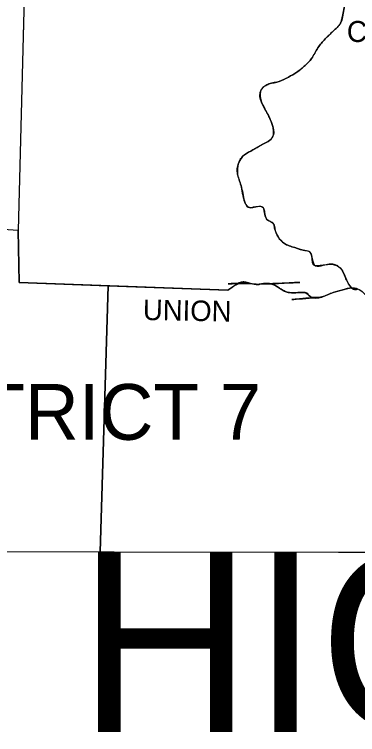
# Model space of a CAD drawing. Extents: x 3046 to 131673, y -8885 to 10756.
# Drawn here: x 103569 to 104255, y 4715 to 6157 of the extents above; entities that cross this region are included whole.
import ezdxf

# ---------------------------------------------------------------- set-up
doc = ezdxf.new("R2010")
doc.units = 0
for name, color, linetype in [('1', 7, 'Continuous'), ('2', 7, 'Continuous'), ('3', 7, 'Continuous'), ('R_Annotation', 7, 'Continuous')]:
    doc.layers.add(name, color=color, linetype=linetype)

msp = doc.modelspace()

# ---------------------------------------------------------------- linework, layer by layer
at = {"layer": '1'}
for points in [[(103588.89674506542, 6217.377333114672), (103576.17745635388, 5724.260297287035), (103444.09253611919, 5733.06595852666), (103443.11412921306, 5696.86490635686), (103267.00090220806, 5707.62738140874)], [(103588.89674506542, 6217.377333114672), (103576.17745635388, 5724.260297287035), (103444.09253611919, 5733.06595852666), (103443.11412921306, 5696.86490635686), (103267.00090220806, 5707.62738140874)], [(102421.65741198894, 5874.934947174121), (102423.61422561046, 5083.403831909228), (106009.47521109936, 5077.533390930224)], [(102421.65741198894, 5874.934947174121), (102423.61422561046, 5083.403831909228), (106009.47521109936, 5077.533390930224)], [(103995.91398108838, 5604.894665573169), (103578.13427001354, 5620.54917462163), (103576.08045633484, 5724.266763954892)], [(103995.91398108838, 5604.894665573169), (103578.13427001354, 5620.54917462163), (103576.08045633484, 5724.266763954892)], [(103756.26641412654, 5613.874433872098), (103740.74359051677, 5081.247549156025)], [(103756.26641412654, 5613.874433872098), (103740.74359051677, 5081.247549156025)]]:
    msp.add_lwpolyline(points, dxfattribs=at)
for points in [[(104237.08427846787, 6257.806639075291), (104234.64524447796, 6196.830789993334), (104227.79639682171, 6166.5001787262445), (104220.94754901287, 6139.104787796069), (104206.2714468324, 6123.450278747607), (104190.61693770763, 6107.795769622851), (104175.94083552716, 6090.184446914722), (104163.2215468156, 6068.659496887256), (104150.50225825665, 6054.961801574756), (104133.86934222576, 6041.264106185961), (104117.23642638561, 6031.4800379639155), (104098.6466969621, 6022.67437649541), (104078.10015365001, 6017.782342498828), (104063.42405146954, 6007.019867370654), (104062.44564456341, 5983.538103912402), (104079.07856055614, 5950.272272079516), (104084.949001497, 5934.61776295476), (104086.90581515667, 5916.028033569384), (104080.05696730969, 5905.2655584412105), (104064.40245818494, 5896.459897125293), (104045.8127287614, 5885.697422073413), (104029.17981292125, 5875.913353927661), (104017.43893111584, 5859.280438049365), (104015.48211745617, 5836.777081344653), (104023.3093719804, 5810.360097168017), (104026.24459235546, 5794.705588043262), (104038.96388110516, 5770.245417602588), (104048.74794925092, 5771.223824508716), (104066.3592718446, 5770.245417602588), (104068.31608550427, 5765.3533836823), (104069.2944924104, 5760.461349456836), (104073.20811969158, 5747.7420608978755), (104087.88422187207, 5736.979585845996), (104089.84103549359, 5727.19551762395), (104098.6466969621, 5708.60578816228), (104113.32279914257, 5695.88649960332), (104124.08527408, 5691.972872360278), (104146.58863097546, 5685.12402455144), (104158.32951278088, 5682.188804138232), (104171.04880133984, 5653.815006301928), (104186.70331042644, 5654.793413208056), (104198.44419223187, 5656.750226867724), (104218.01232863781, 5651.858192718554), (104226.81798991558, 5640.117311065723), (104235.62365138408, 5620.54917462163), (104247.36453318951, 5606.851479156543), (104255.19178771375, 5606.851479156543)], [(104237.08427846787, 6257.806639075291), (104234.64524447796, 6196.830789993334), (104227.79639682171, 6166.5001787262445), (104220.94754901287, 6139.104787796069), (104206.2714468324, 6123.450278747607), (104190.61693770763, 6107.795769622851), (104175.94083552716, 6090.184446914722), (104163.2215468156, 6068.659496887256), (104150.50225825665, 6054.961801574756), (104133.86934222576, 6041.264106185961), (104117.23642638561, 6031.4800379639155), (104098.6466969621, 6022.67437649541), (104078.10015365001, 6017.782342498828), (104063.42405146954, 6007.019867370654), (104062.44564456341, 5983.538103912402), (104079.07856055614, 5950.272272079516), (104084.949001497, 5934.61776295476), (104086.90581515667, 5916.028033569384), (104080.05696730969, 5905.2655584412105), (104064.40245818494, 5896.459897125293), (104045.8127287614, 5885.697422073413), (104029.17981292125, 5875.913353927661), (104017.43893111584, 5859.280438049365), (104015.48211745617, 5836.777081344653), (104023.3093719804, 5810.360097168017), (104026.24459235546, 5794.705588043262), (104038.96388110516, 5770.245417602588), (104048.74794925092, 5771.223824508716), (104066.3592718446, 5770.245417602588), (104068.31608550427, 5765.3533836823), (104069.2944924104, 5760.461349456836), (104073.20811969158, 5747.7420608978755), (104087.88422187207, 5736.979585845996), (104089.84103549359, 5727.19551762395), (104098.6466969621, 5708.60578816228), (104113.32279914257, 5695.88649960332), (104124.08527408, 5691.972872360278), (104146.58863097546, 5685.12402455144), (104158.32951278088, 5682.188804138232), (104171.04880133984, 5653.815006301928), (104186.70331042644, 5654.793413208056), (104198.44419223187, 5656.750226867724), (104218.01232863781, 5651.858192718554), (104226.81798991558, 5640.117311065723), (104235.62365138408, 5620.54917462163), (104247.36453318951, 5606.851479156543), (104255.19178771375, 5606.851479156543)], [(103995.91398108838, 5604.894665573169), (104011.56849017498, 5615.657140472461), (104026.24459235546, 5621.5275813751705), (104040.92069472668, 5618.592361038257), (104056.5752036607, 5616.635547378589), (104070.27289912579, 5618.592361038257), (104087.88422187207, 5615.657140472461), (104102.56032420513, 5606.851479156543), (104119.19324004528, 5600.0026314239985), (104135.82615588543, 5600.0026314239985), (104150.50225825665, 5600.0026314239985), (104163.2215468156, 5591.196970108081), (104186.70331042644, 5592.175376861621), (104206.2714468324, 5600.0026314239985), (104225.83958316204, 5605.873072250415), (104252.25656722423, 5608.80829281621), (104275.73833087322, 5592.175376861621), (104292.37124671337, 5578.477681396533), (104306.06894214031, 5562.823172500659), (104315.85301032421, 5545.2118497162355), (104326.6154852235, 5535.427781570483), (104344.22680796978, 5528.578933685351), (104357.92450343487, 5525.643713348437), (104374.55741946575, 5520.7516791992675), (104383.36308070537, 5516.838051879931), (104391.19033526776, 5498.2483224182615), (104403.90962378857, 5472.809745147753), (104428.36979438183, 5464.004083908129), (104458.70040564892, 5475.744965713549), (104483.16057605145, 5482.593813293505), (104500.77189875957, 5488.46425427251), (104511.53437388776, 5492.377881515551), (104521.31844207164, 5493.356288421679), (104518.38322150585, 5495.313102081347), (104530.12410331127, 5498.2483224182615), (104540.88657824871, 5490.421067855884), (104547.73542605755, 5479.658592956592), (104559.47630790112, 5464.004083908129), (104570.23878280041, 5450.306388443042), (104581.00125792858, 5445.414354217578), (104591.76373282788, 5451.2847951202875), (104606.43983500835, 5446.392761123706), (104619.15912375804, 5441.500726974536), (104633.83522593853, 5437.587099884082), (104646.55451465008, 5436.608692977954), (104663.18743045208, 5432.695065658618), (104675.90671904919, 5425.846218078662), (104687.64760089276, 5418.99737019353), (104699.38848269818, 5406.27808163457), (104711.12936450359, 5386.7099453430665), (104715.04299178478, 5371.05543621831), (104728.74068724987, 5355.400927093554), (104741.45997596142, 5355.400927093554), (104760.0497054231, 5329.962349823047), (104766.89855307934, 5320.178281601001), (104781.57465545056, 5302.56695889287), (104792.33713034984, 5302.56695889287), (104812.88367347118, 5298.653331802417)], [(103995.91398108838, 5604.894665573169), (104011.56849017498, 5615.657140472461), (104026.24459235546, 5621.5275813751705), (104040.92069472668, 5618.592361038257), (104056.5752036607, 5616.635547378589), (104070.27289912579, 5618.592361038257), (104087.88422187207, 5615.657140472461), (104102.56032420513, 5606.851479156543), (104119.19324004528, 5600.0026314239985), (104135.82615588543, 5600.0026314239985), (104150.50225825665, 5600.0026314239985), (104163.2215468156, 5591.196970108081), (104186.70331042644, 5592.175376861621), (104206.2714468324, 5600.0026314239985), (104225.83958316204, 5605.873072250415), (104252.25656722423, 5608.80829281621), (104275.73833087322, 5592.175376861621), (104292.37124671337, 5578.477681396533), (104306.06894214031, 5562.823172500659), (104315.85301032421, 5545.2118497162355), (104326.6154852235, 5535.427781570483), (104344.22680796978, 5528.578933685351), (104357.92450343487, 5525.643713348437), (104374.55741946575, 5520.7516791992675), (104383.36308070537, 5516.838051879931), (104391.19033526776, 5498.2483224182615), (104403.90962378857, 5472.809745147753), (104428.36979438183, 5464.004083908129), (104458.70040564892, 5475.744965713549), (104483.16057605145, 5482.593813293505), (104500.77189875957, 5488.46425427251), (104511.53437388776, 5492.377881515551), (104521.31844207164, 5493.356288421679), (104518.38322150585, 5495.313102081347), (104530.12410331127, 5498.2483224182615), (104540.88657824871, 5490.421067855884), (104547.73542605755, 5479.658592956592), (104559.47630790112, 5464.004083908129), (104570.23878280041, 5450.306388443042), (104581.00125792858, 5445.414354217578), (104591.76373282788, 5451.2847951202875), (104606.43983500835, 5446.392761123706), (104619.15912375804, 5441.500726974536), (104633.83522593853, 5437.587099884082), (104646.55451465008, 5436.608692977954), (104663.18743045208, 5432.695065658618), (104675.90671904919, 5425.846218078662), (104687.64760089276, 5418.99737019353), (104699.38848269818, 5406.27808163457), (104711.12936450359, 5386.7099453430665), (104715.04299178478, 5371.05543621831), (104728.74068724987, 5355.400927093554), (104741.45997596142, 5355.400927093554), (104760.0497054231, 5329.962349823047), (104766.89855307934, 5320.178281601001), (104781.57465545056, 5302.56695889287), (104792.33713034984, 5302.56695889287), (104812.88367347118, 5298.653331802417)]]:
    msp.add_spline(points, degree=3, dxfattribs=at)
at = {"layer": 'R_Annotation'}
for p, q in [((103588.89674506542, 6217.377333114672), (103576.08045633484, 5724.266763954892)), ((103756.26641412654, 5613.874433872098), (103740.74359051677, 5081.247549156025)), ((103740.74359051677, 5081.247549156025), (103756.26641412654, 5613.874433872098)), ((103995.91398108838, 5604.894665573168), (103756.26641412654, 5613.874433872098)), ((103756.26641412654, 5613.874433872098), (103995.91398108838, 5604.894665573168)), ((104011.56849017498, 5615.657140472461), (104026.24459235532, 5621.527581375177)), ((104026.24459235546, 5621.5275813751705), (104031.41696694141, 5620.766988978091)), ((104031.41696694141, 5620.76698897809), (104033.55187765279, 5620.254488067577)), ((104034.81262439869, 5619.933282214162), (104037.22442127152, 5619.330202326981)), ((104063.42509927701, 5617.470504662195), (104066.84895005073, 5618.2204441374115)), ((104068.49074441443, 5618.473637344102), (104070.27289912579, 5618.592361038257)), ((104070.27289912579, 5618.592361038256), (104079.08503790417, 5618.058886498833)), ((104079.08503790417, 5618.058886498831), (104087.88422187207, 5615.657140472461)), ((104091.813874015, 5613.660706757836), (104095.39345936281, 5611.345137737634)), ((104097.23152067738, 5610.087265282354), (104098.8874515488, 5608.984154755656)), ((104225.83958316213, 5605.87307225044), (104243.53112397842, 5610.17400937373)), ((104102.56032420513, 5606.851479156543), (104109.1567881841, 5603.198928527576)), ((104109.1567881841, 5603.198928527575), (104110.65170703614, 5602.414280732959)), ((104110.65170703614, 5602.414280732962), (104116.58782989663, 5600.255141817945)), ((104116.58782989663, 5600.255141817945), (104119.19324004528, 5600.0026314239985)), ((104153.97707314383, 5598.759042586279), (104156.9608794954, 5595.952589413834)), ((104188.87412338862, 5592.977191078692), (104191.60593975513, 5594.068024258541)), ((104191.60593975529, 5594.068024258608), (104196.4626671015, 5596.12803246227)), ((104196.46266710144, 5596.128032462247), (104201.3317502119, 5598.168526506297)), ((104201.33175021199, 5598.168526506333), (104204.7990627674, 5599.492504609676)), ((104204.7990627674, 5599.492504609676), (104206.2714468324, 5600.002631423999)), ((104206.2714468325, 5600.002631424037), (104215.69116409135, 5602.964978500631)), ((104215.69116409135, 5602.96497850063), (104225.83958316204, 5605.873072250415)), ((104159.89519736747, 5592.969741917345), (104161.38718769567, 5591.898698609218)), ((104161.38718769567, 5591.898698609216), (104163.2215468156, 5591.196970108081)), ((104174.99264871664, 5590.176320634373), (104180.97773212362, 5590.725886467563)), ((104180.97773212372, 5590.725886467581), (104183.73743536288, 5591.2914970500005)), ((104183.73743536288, 5591.291497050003), (104186.7033104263, 5592.175376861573)), ((104186.70331042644, 5592.175376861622), (104188.87412338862, 5592.977191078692)), ((103113.39078486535, 5082.274593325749), (103740.74359051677, 5081.247549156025)), ((103740.74359051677, 5081.247549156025), (104880.7243214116, 5079.381277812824))]:
    msp.add_line(p, q, dxfattribs=at)
for points in [[(103576.08045633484, 5724.266763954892), (103444.09253611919, 5733.06595852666), (103443.11412921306, 5696.86490635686), (103267.00090220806, 5707.62738140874)], [(103576.08045633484, 5724.266763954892), (103578.13427001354, 5620.54917462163), (103756.26641412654, 5613.874433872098)], [(103756.26641412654, 5613.874433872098), (103578.13427001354, 5620.54917462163), (103576.08045633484, 5724.266763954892)], [(104255.4074246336, 5607.249735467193), (104255.19178771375, 5606.851479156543)]]:
    msp.add_lwpolyline(points, dxfattribs=at)
for points in [[(104062.76730762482, 5895.513607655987), (104064.40245818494, 5896.459897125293), (104080.05696730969, 5905.2655584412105), (104086.90581515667, 5916.028033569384), (104087.31956126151, 5920.659311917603), (104087.06390239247, 5925.379459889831), (104086.23999649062, 5930.07132704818), (104084.949001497, 5934.61776295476), (104079.07856055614, 5950.272272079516), (104075.1593298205, 5958.712599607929), (104070.80542871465, 5966.985054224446), (104066.42986453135, 5975.217575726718), (104062.44564456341, 5983.538103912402), (104059.98287036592, 5995.270110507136), (104060.81533309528, 6001.34864555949), (104063.42405146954, 6007.019867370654), (104064.88231507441, 6008.975697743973), (104066.46582220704, 6010.725926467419), (104069.9730795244, 6013.6719131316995), (104078.10015365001, 6017.782342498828), (104083.25050255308, 6019.193255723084), (104088.48277216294, 6020.111812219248), (104093.66036834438, 6021.08864235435), (104098.6466969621, 6022.67437649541), (104117.23642638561, 6031.4800379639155), (104133.86934222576, 6041.264106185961), (104150.50225825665, 6054.961801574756), (104163.2215468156, 6068.659496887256), (104166.64652242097, 6073.894243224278), (104169.60202341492, 6079.422534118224), (104172.54710828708, 6084.950543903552), (104175.94083552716, 6090.184446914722), (104190.61693770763, 6107.795769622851), (104198.42488536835, 6115.643399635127), (104206.2714468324, 6123.450278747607), (104214.26704404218, 6130.707505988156), (104217.97779579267, 6134.58586323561), (104220.94754901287, 6139.104787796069), (104221.71287693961, 6140.745184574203), (104222.3945192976, 6142.403100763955), (104223.53993208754, 6145.764682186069), (104225.19156342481, 6152.623176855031), (104227.79639682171, 6166.5001787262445), (104231.68915429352, 6181.578272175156), (104234.64524447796, 6196.830789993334), (104235.34530635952, 6204.41818446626), (104235.85551729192, 6212.010610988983), (104236.45989263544, 6227.20668069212), (104237.07900152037, 6257.6165302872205)], [(104243.53112397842, 5610.174009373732), (104235.62365138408, 5620.54917462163), (104233.24202139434, 5625.406227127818), (104231.19415954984, 5630.3451736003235), (104229.15962825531, 5635.278154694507), (104226.81798991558, 5640.117311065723), (104223.25149066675, 5646.369532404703), (104218.01232863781, 5651.858192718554), (104215.62705542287, 5653.408541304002), (104213.21806295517, 5654.646573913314), (104208.34164800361, 5656.273840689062), (104198.44419223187, 5656.750226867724), (104186.70331042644, 5654.793413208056), (104178.87479352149, 5653.910495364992), (104171.04880133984, 5653.815006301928), (104167.97501701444, 5655.115314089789), (104166.1454655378, 5658.139096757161), (104164.57852300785, 5667.193803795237), (104163.06689750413, 5676.652561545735), (104159.99570774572, 5681.409088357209), (104158.32951278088, 5682.188804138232), (104146.58863097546, 5685.12402455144), (104124.08527408, 5691.972872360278), (104113.32279914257, 5695.88649960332), (104105.2078176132, 5701.129294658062), (104101.76044937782, 5704.643393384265), (104098.6466969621, 5708.60578816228), (104093.56590576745, 5717.697563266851), (104089.84103549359, 5727.19551762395), (104089.22899980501, 5729.607461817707), (104088.91159864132, 5732.113622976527), (104088.56971249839, 5734.606748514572), (104087.88422187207, 5736.979585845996), (104084.91370739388, 5740.200597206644), (104080.49755427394, 5742.312712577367), (104076.10570940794, 5744.448883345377), (104073.20811969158, 5747.7420608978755), (104069.2944924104, 5760.461349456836), (104068.31608550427, 5765.3533836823), (104067.8426010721, 5767.97744058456), (104066.3592718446, 5770.245417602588), (104065.27008352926, 5770.944299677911), (104064.17768793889, 5771.488145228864), (104061.9847075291, 5772.170731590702), (104057.57601796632, 5772.3355191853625), (104053.15612469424, 5771.699857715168), (104050.94913964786, 5771.381882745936), (104048.74794925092, 5771.223824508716), (104046.29675386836, 5770.811701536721), (104043.84597519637, 5770.085771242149), (104041.40016651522, 5769.684265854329), (104038.96388110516, 5770.245417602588), (104037.34698979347, 5771.1944231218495), (104035.89505226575, 5772.274105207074), (104033.43858512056, 5774.779748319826), (104029.98310837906, 5780.855895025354), (104027.8381958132, 5787.741845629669), (104026.24459235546, 5794.705588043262), (104025.44489193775, 5798.627029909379), (104024.7750640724, 5802.562752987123), (104023.3093719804, 5810.360097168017), (104021.49284116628, 5816.984858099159), (104019.37642678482, 5823.57664696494), (104017.26967137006, 5830.164406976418), (104015.48211745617, 5836.777081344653), (104014.80890854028, 5847.990113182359), (104017.43893111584, 5859.280438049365), (104019.49373283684, 5864.182851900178), (104022.046241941, 5868.767268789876), (104025.23031608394, 5872.766499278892), (104029.17981292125, 5875.913353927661), (104045.8127287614, 5885.697422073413), (104062.76730762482, 5895.513607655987)], [(104060.00072456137, 5616.792289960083), (104063.42509927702, 5617.470504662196), (104063.42509927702, 5617.470504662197)], [(104037.22442127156, 5619.330202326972), (104037.22442127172, 5619.330202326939), (104040.92069472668, 5618.592361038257), (104040.92069472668, 5618.592361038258)], [(104243.53112397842, 5610.17400937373), (104225.83958316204, 5605.873072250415), (104206.2714468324, 5600.0026314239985), (104201.33175021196, 5598.168526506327), (104196.46266710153, 5596.128032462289), (104191.60593975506, 5594.068024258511), (104186.70331042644, 5592.175376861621), (104180.97773212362, 5590.725886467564), (104174.99264871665, 5590.176320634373), (104168.99245526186, 5590.38168122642), (104163.2215468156, 5591.196970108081), (104159.89519736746, 5592.969741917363), (104156.96087949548, 5595.952589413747), (104153.97707314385, 5598.759042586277), (104150.50225825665, 5600.0026314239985), (104135.82615588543, 5600.0026314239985), (104119.19324004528, 5600.0026314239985), (104110.65170703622, 5602.414280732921), (104102.56032420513, 5606.851479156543), (104098.88745154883, 5608.984154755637), (104095.39345936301, 5611.345137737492), (104091.81387401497, 5613.6607067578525), (104087.88422187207, 5615.657140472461), (104070.27289912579, 5618.592361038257), (104066.8489500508, 5618.220444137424), (104063.42509927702, 5617.470504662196), (104060.00072456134, 5616.79228996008), (104056.5752036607, 5616.635547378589), (104040.92069472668, 5618.592361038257), (104037.22442127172, 5619.330202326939), (104033.55187765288, 5620.25448806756), (104026.24459235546, 5621.5275813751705), (104011.56849017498, 5615.657140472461), (103995.91398108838, 5604.894665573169)], [(104033.55187765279, 5620.254488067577), (104033.55187765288, 5620.25448806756), (104034.81262439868, 5619.933282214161)], [(104066.84895005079, 5618.220444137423), (104066.8489500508, 5618.220444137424), (104068.49074441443, 5618.473637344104)], [(104087.88422187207, 5615.657140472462), (104087.88422187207, 5615.657140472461), (104091.81387401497, 5613.6607067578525), (104091.81387401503, 5613.6607067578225)], [(104095.39345936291, 5611.345137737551), (104095.39345936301, 5611.345137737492), (104097.2315206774, 5610.087265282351)], [(104098.88745154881, 5608.984154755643), (104098.88745154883, 5608.984154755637), (104102.56032420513, 5606.851479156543)], [(104255.19178771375, 5606.851479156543), (104247.36453318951, 5606.851479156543), (104243.53112397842, 5610.174009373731)], [(104119.19324004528, 5600.0026314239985), (104135.82615588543, 5600.0026314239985), (104150.50225825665, 5600.0026314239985)], [(104150.50225825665, 5600.002631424), (104153.97707314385, 5598.759042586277), (104153.97707314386, 5598.759042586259)], [(104156.96087949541, 5595.952589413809), (104156.96087949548, 5595.952589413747), (104159.89519736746, 5592.969741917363), (104159.89519736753, 5592.9697419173)], [(104168.99245526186, 5590.381681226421), (104168.99245526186, 5590.38168122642), (104174.99264871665, 5590.176320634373), (104174.99264871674, 5590.176320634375)], [(104163.22154681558, 5591.196970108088), (104163.2215468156, 5591.196970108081), (104168.99245526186, 5590.381681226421)]]:
    msp.add_spline(points, degree=3, dxfattribs=at)
for points in [[(103995.91398108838, 5604.894665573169), (104000.72916449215, 5609.118662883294), (104005.904907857, 5612.323759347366), (104011.56849017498, 5615.657140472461), (104011.56849017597, 5615.657140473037), (104011.56849017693, 5615.657140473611), (104011.5684901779, 5615.657140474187)], [(104040.92069472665, 5618.592361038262), (104040.92069472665, 5618.592361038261), (104040.92069472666, 5618.592361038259), (104040.92069472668, 5618.592361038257), (104046.13623311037, 5617.819287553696), (104051.36642416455, 5617.021548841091), (104056.5752036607, 5616.635547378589), (104057.71730412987, 5616.550910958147), (104058.85910986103, 5616.628144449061), (104060.00072456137, 5616.792289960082)]]:
    msp.add_open_spline(points, degree=3, dxfattribs=at)

# ---------------------------------------------------------------- texts
at = {"layer": '2'}
for s, height, rotation, p in [('CALHOUN', 42.07344995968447, 359.36340559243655, (104233.66683772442, 6101.925328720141)), ('CALHOUN', 42.07344995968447, 359.36340559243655, (104233.66683772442, 6101.925328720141)), ('UNION', 41.09308632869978, 358.9583722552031, (103825.67119483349, 5545.2118497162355)), ('UNION', 41.09308632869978, 358.9583722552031, (103825.67119483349, 5545.2118497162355))]:
    msp.add_text(s, height=height, rotation=rotation, dxfattribs=at).set_placement(p)
msp.add_text('ARKANSAS HIGHWAY DISTRICT 7', height=360, dxfattribs=at).set_placement((100941.11164748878, 4720.468611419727))
at = {"layer": '3'}
msp.add_text('DISTRICT 7', height=111.53837717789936, dxfattribs=at).set_placement((103250.36798621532, 5305.502179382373))
msp.add_text('DISTRICT 7', height=111.53837717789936, dxfattribs=at).set_placement((103250.36798621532, 5305.502179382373))

doc.saveas('drawing.dxf')
